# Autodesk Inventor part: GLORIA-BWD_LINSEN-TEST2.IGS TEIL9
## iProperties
Created: 2005-04
Part Number: GLORIA-BWD_LINSEN-TEST2.IGS TEIL9
Document SubType Name: Modeling
Designer: Nordmeyer
Manufacturer: Standard
Standards Organization: Custom
Author: Nordmeyer
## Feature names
1. Erst1
